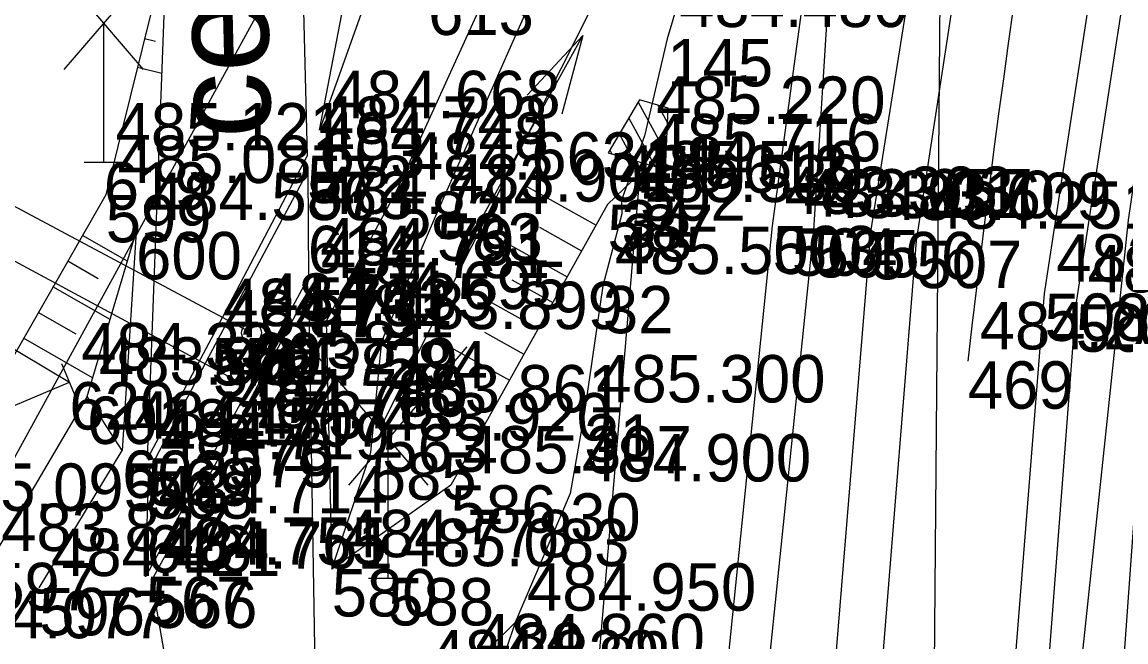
# Model space of a CAD drawing. Extents: x -874038 to -859694, y -1059487 to -1049069.
# Drawn here: x -866901.73 to -866873.81, y -1050811.61 to -1050795.92 of the extents above; entities that cross this region are included whole.
import ezdxf

# ---------------------------------------------------------------- set-up
doc = ezdxf.new("R2010")
doc.units = 0
for name, color, linetype in [('Vrstva 1', 7, 'Continuous'), ('Vrstva 13', 7, 'Continuous'), ('Vrstva 23', 7, 'Continuous'), ('Vrstva 28', 7, 'Continuous'), ('Vrstva 31', 7, 'Continuous'), ('Vrstva 32', 7, 'Continuous'), ('Vrstva 4', 7, 'Continuous'), ('Vrstva 44', 7, 'Continuous'), ('Vrstva 48', 7, 'Continuous'), ('Vrstva 49', 7, 'Continuous'), ('Vrstva 51', 7, 'Continuous'), ('Vrstva 6', 7, 'Continuous'), ('Vrstva 60', 7, 'Continuous'), ('Vrstva 61', 7, 'Continuous'), ('Vrstva 63', 7, 'Continuous'), ('Vrstva 7', 7, 'Continuous')]:
    doc.layers.add(name, color=color, linetype=linetype)

msp = doc.modelspace()

# ---------------------------------------------------------------- linework, layer by layer
at = {"layer": 'Vrstva 1'}
msp.add_line((-866954.595, -1050772.5), (-866895.93, -1050803.784), dxfattribs=at)
msp.add_circle((-866895.93, -1050803.784), 0.25, dxfattribs=at)
msp.add_arc((-866539.48, -1050843.456), 340.562, 163.73547, 173.43306, dxfattribs=at)
at = {"layer": 'Vrstva 13'}
for p, q in [((-866882.745, -1050801.081), (-866881.765, -1050793.85)), ((-866881.706, -1050801.186), (-866881.246, -1050793.897)), ((-866890.45, -1050801.514), (-866887.55, -1050796.262)), ((-866884.839, -1050821.549), (-866882.745, -1050801.081)), ((-866883.811, -1050821.656), (-866881.706, -1050801.186)), ((-866873.377, -1050805.329), (-866874.96, -1050827.043))]:
    msp.add_line(p, q, dxfattribs=at)
for points in [[(-866883.26, -1050790.618), (-866884.83, -1050791.288), (-866885.841, -1050792.599), (-866892.622, -1050806.103)], [(-866888.954, -1050797.77), (-866887.55, -1050796.262), (-866888.079, -1050798.253)]]:
    msp.add_lwpolyline(points, dxfattribs=at)
at = {"layer": 'Vrstva 23'}
msp.add_lwpolyline([(-866860.091, -1050744.519), (-866863.217, -1050755.466), (-866865.293, -1050757.745), (-866868.888, -1050772.679), (-866871.977, -1050788.759), (-866873.748, -1050800.936), (-866875.048, -1050813.205), (-866876.041, -1050829.553), (-866876.177, -1050845.923), (-866875.472, -1050862.297), (-866873.902, -1050878.655), (-866871.491, -1050894.865), (-866868.278, -1050910.955), (-866864.193, -1050926.852), (-866859.318, -1050942.487)], dxfattribs=at)
at = {"layer": 'Vrstva 28'}
for points in [[(-866881.37, -1050788.45), (-866881.18, -1050787.98), (-866881.44, -1050787.55), (-866882.31, -1050787.39), (-866883.05, -1050788.18), (-866884.05, -1050790.89), (-866884.17, -1050792.18), (-866885.41, -1050796.35), (-866885.99, -1050798.8), (-866886.57, -1050800.43), (-866886.56, -1050800.78), (-866887.04, -1050802.6), (-866887.51, -1050805.85), (-866887.87, -1050807.85), (-866889.26, -1050811.12), (-866890.17, -1050813.82), (-866890.72, -1050816.67), (-866890.58, -1050818.77), (-866890.54, -1050824.2), (-866890.49, -1050831.84), (-866890.38, -1050847.8), (-866888.25, -1050865.72)], [(-866881.37, -1050788.45), (-866881.18, -1050787.98), (-866881.44, -1050787.55), (-866882.31, -1050787.39), (-866883.05, -1050788.18), (-866884.05, -1050790.89), (-866884.17, -1050792.18), (-866885.41, -1050796.35), (-866885.99, -1050798.8), (-866886.57, -1050800.43), (-866886.56, -1050800.78), (-866887.04, -1050802.6), (-866887.51, -1050805.85), (-866887.87, -1050807.85), (-866889.26, -1050811.12)], [(-866889.26, -1050811.12), (-866890.56, -1050812.4), (-866891.72, -1050812.81)]]:
    msp.add_lwpolyline(points, dxfattribs=at)
at = {"layer": 'Vrstva 31'}
for p, q in [((-866886.113, -1050797.89), (-866886.903, -1050799.229)), ((-866886.148, -1050797.948), (-866885.44, -1050799.252)), ((-866885.392, -1050798.103), (-866886.113, -1050797.89)), ((-866885.647, -1050798.027), (-866885.407, -1050798.47)), ((-866886.387, -1050798.353), (-866885.719, -1050799.579)), ((-866885.457, -1050799.656), (-866885.392, -1050798.103)), ((-866886.624, -1050798.755), (-866886.264, -1050799.418)), ((-866886.863, -1050799.16), (-866886.81, -1050799.256)), ((-866886.903, -1050799.229), (-866885.457, -1050799.656))]:
    msp.add_line(p, q, dxfattribs=at)
at = {"layer": 'Vrstva 32'}
for points in [[(-866881.37, -1050788.45), (-866881.18, -1050787.98), (-866881.44, -1050787.55), (-866882.31, -1050787.39), (-866883.05, -1050788.18), (-866884.05, -1050790.89), (-866884.17, -1050792.18), (-866885.41, -1050796.35), (-866885.99, -1050798.8), (-866886.57, -1050800.43), (-866886.56, -1050800.78), (-866887.04, -1050802.6), (-866887.51, -1050805.85), (-866887.87, -1050807.85), (-866889.26, -1050811.12), (-866890.17, -1050813.82), (-866890.72, -1050816.67), (-866890.58, -1050818.77)], [(-866881.37, -1050788.45), (-866881.18, -1050787.98), (-866881.44, -1050787.55), (-866882.31, -1050787.39), (-866883.05, -1050788.18), (-866884.05, -1050790.89), (-866884.17, -1050792.18), (-866885.41, -1050796.35), (-866885.99, -1050798.8), (-866886.57, -1050800.43), (-866886.56, -1050800.78), (-866887.04, -1050802.6), (-866887.51, -1050805.85), (-866887.87, -1050807.85), (-866889.26, -1050811.12), (-866890.17, -1050813.82), (-866890.72, -1050816.67), (-866890.58, -1050818.77), (-866890.49, -1050831.84), (-866890.38, -1050847.8), (-866888.25, -1050865.72)], [(-866881.37, -1050788.45), (-866881.18, -1050787.98), (-866881.44, -1050787.55), (-866882.31, -1050787.39), (-866883.05, -1050788.18), (-866884.05, -1050790.89), (-866884.17, -1050792.18), (-866885.41, -1050796.35), (-866885.99, -1050798.8), (-866886.57, -1050800.43), (-866886.56, -1050800.78), (-866887.04, -1050802.6), (-866887.51, -1050805.85), (-866887.87, -1050807.85), (-866889.26, -1050811.12)], [(-866889.26, -1050811.12), (-866890.56, -1050812.4), (-866891.72, -1050812.81)]]:
    msp.add_lwpolyline(points, dxfattribs=at)
at = {"layer": 'Vrstva 4'}
for p, q in [((-866874.869, -1050762.04), (-866892.274, -1050800.212)), ((-866891.238, -1050800.767), (-866874.734, -1050763.477)), ((-866876.724, -1050779.104), (-866880.273, -1050801.234)), ((-866879.105, -1050801.456), (-866875.741, -1050779.509)), ((-866871.451, -1050779.65), (-866875.077, -1050803.067)), ((-866875.867, -1050802.793), (-866872.377, -1050779.959)), ((-866901.668, -1050793.623), (-866898.668, -1050797.123)), ((-866900.668, -1050797.123), (-866897.668, -1050793.623)), ((-866899.668, -1050799.473), (-866899.668, -1050795.973)), ((-866900.168, -1050799.473), (-866899.168, -1050799.473)), ((-866896.908, -1050804.202), (-866894.504, -1050799.708)), ((-866894.504, -1050799.708), (-866894.488, -1050802.383)), ((-866892.274, -1050800.212), (-866894.044, -1050803.489)), ((-866904.108, -1050800.796), (-866896.518, -1050804.882)), ((-866892.631, -1050803.995), (-866891.238, -1050800.767)), ((-866900.09, -1050805.401), (-866898.851, -1050801.235)), ((-866898.851, -1050801.235), (-866899.201, -1050806.767)), ((-866880.273, -1050801.234), (-866882.525, -1050828.821)), ((-866881.311, -1050828.858), (-866879.105, -1050801.456)), ((-866894.488, -1050802.383), (-866896.556, -1050806.207)), ((-866877.931, -1050828.807), (-866875.867, -1050802.793)), ((-866875.077, -1050803.067), (-866877.028, -1050828.61)), ((-866894.044, -1050803.489), (-866893.901, -1050809.767)), ((-866898.531, -1050807.291), (-866896.908, -1050804.202)), ((-866894.471, -1050804.144), (-866891.471, -1050807.644)), ((-866893.471, -1050807.644), (-866890.471, -1050804.144)), ((-866892.913, -1050806.813), (-866892.631, -1050803.995)), ((-866900.09, -1050805.401), (-866902.564, -1050809.609)), ((-866899.201, -1050806.767), (-866900.09, -1050805.401)), ((-866896.556, -1050806.207), (-866898.608, -1050809.959)), ((-866892.471, -1050809.994), (-866892.471, -1050806.494)), ((-866901.302, -1050810.243), (-866899.201, -1050806.767)), ((-866893.901, -1050809.767), (-866892.913, -1050806.813)), ((-866898.608, -1050809.959), (-866898.531, -1050807.291)), ((-866892.971, -1050809.994), (-866891.971, -1050809.994))]:
    msp.add_line(p, q, dxfattribs=at)
msp.add_lwpolyline([(-866891.558, -1050791.236), (-866894.209, -1050798.657), (-866892.733, -1050790.985)], dxfattribs=at)
at = {"layer": 'Vrstva 44'}
msp.add_lwpolyline([(-866912.752, -1050826.723), (-866890.904, -1050786.8), (-866874.15, -1050746.784), (-866858.678, -1050710.211), (-866845.122, -1050668.894)], dxfattribs=at)
at = {"layer": 'Vrstva 48'}
for p, q in [((-866898.355, -1050796.414), (-866898.636, -1050796.345)), ((-866898.197, -1050797.225), (-866898.817, -1050797.071)), ((-866889.023, -1050800.05), (-866887.212, -1050801.061)), ((-866888.647, -1050801.118), (-866887.578, -1050801.715)), ((-866899.071, -1050801.975), (-866900.207, -1050801.324)), ((-866889.696, -1050801.39), (-866887.943, -1050802.369)), ((-866899.806, -1050802.418), (-866900.58, -1050801.975)), ((-866889.343, -1050802.446), (-866888.309, -1050803.024)), ((-866899.51, -1050803.452), (-866900.953, -1050802.625)), ((-866890.37, -1050802.731), (-866888.674, -1050803.678)), ((-866900.368, -1050803.825), (-866901.326, -1050803.276)), ((-866899.95, -1050804.929), (-866901.699, -1050803.927)), ((-866890.039, -1050803.774), (-866889.039, -1050804.332)), ((-866891.043, -1050804.072), (-866889.405, -1050804.987))]:
    msp.add_line(p, q, dxfattribs=at)
at = {"layer": 'Vrstva 49'}
for points in [[(-866898.079, -1050794.1), (-866899.618, -1050800.297), (-866904.374, -1050808.594)], [(-866887.646, -1050855.275), (-866888.765, -1050831.266), (-866886.099, -1050799.75), (-866886.924, -1050800.544), (-866890.89, -1050807.647), (-866893.901, -1050809.767)]]:
    msp.add_lwpolyline(points, dxfattribs=at)
at = {"layer": 'Vrstva 51'}
for p, q in [((-866898.565, -1050806.967), (-866898.079, -1050794.1)), ((-866894.652, -1050794.2), (-866894.525, -1050799.306)), ((-866894.525, -1050799.306), (-866896.944, -1050803.919)), ((-866894.477, -1050802.704), (-866896.511, -1050806.501)), ((-866894.277, -1050814.763), (-866894.477, -1050802.704)), ((-866896.944, -1050803.919), (-866898.565, -1050806.967)), ((-866896.511, -1050806.501), (-866898.458, -1050810.057)), ((-866898.458, -1050810.057), (-866897.206, -1050817.362))]:
    msp.add_line(p, q, dxfattribs=at)
at = {"layer": 'Vrstva 6'}
msp.add_line((-866906.348, -1050801.577), (-866900.537, -1050805.036), dxfattribs=at)
at = {"layer": 'Vrstva 60'}
for p, q in [((-866885.41, -1050796.35), (-866885.41, -1050796.35)), ((-866894.209, -1050798.657), (-866894.209, -1050798.657)), ((-866885.99, -1050798.8), (-866885.99, -1050798.8)), ((-866899.668, -1050799.473), (-866899.668, -1050799.473)), ((-866894.525, -1050799.306), (-866894.525, -1050799.306)), ((-866894.504, -1050799.708), (-866894.504, -1050799.708)), ((-866886.099, -1050799.75), (-866886.099, -1050799.75)), ((-866899.618, -1050800.297), (-866899.618, -1050800.297)), ((-866892.274, -1050800.212), (-866892.274, -1050800.212)), ((-866886.924, -1050800.544), (-866886.924, -1050800.544)), ((-866886.57, -1050800.43), (-866886.57, -1050800.43)), ((-866891.238, -1050800.767), (-866891.238, -1050800.767)), ((-866886.56, -1050800.78), (-866886.56, -1050800.78)), ((-866894.506, -1050801.079), (-866894.506, -1050801.079)), ((-866882.745, -1050801.081), (-866882.745, -1050801.081)), ((-866882.26, -1050801.145), (-866882.26, -1050801.145)), ((-866898.851, -1050801.235), (-866898.851, -1050801.235)), ((-866881.706, -1050801.186), (-866881.706, -1050801.186)), ((-866880.273, -1050801.234), (-866880.273, -1050801.234)), ((-866879.105, -1050801.456), (-866879.105, -1050801.456)), ((-866894.488, -1050802.383), (-866894.488, -1050802.383)), ((-866894.477, -1050802.704), (-866894.477, -1050802.704)), ((-866887.04, -1050802.6), (-866887.04, -1050802.6)), ((-866875.867, -1050802.793), (-866875.867, -1050802.793)), ((-866875.077, -1050803.067), (-866875.077, -1050803.067)), ((-866894.044, -1050803.489), (-866894.044, -1050803.489)), ((-866896.944, -1050803.919), (-866896.944, -1050803.919)), ((-866895.93, -1050803.784), (-866895.93, -1050803.784)), ((-866896.908, -1050804.202), (-866896.908, -1050804.202)), ((-866892.631, -1050803.995), (-866892.631, -1050803.995)), ((-866877.806, -1050804.508), (-866877.806, -1050804.508)), ((-866900.537, -1050805.036), (-866900.537, -1050805.036)), ((-866900.09, -1050805.401), (-866900.09, -1050805.401)), ((-866896.809, -1050805.421), (-866896.809, -1050805.421)), ((-866887.51, -1050805.85), (-866887.51, -1050805.85)), ((-866892.622, -1050806.103), (-866892.622, -1050806.103)), ((-866896.556, -1050806.207), (-866896.556, -1050806.207)), ((-866896.511, -1050806.501), (-866896.511, -1050806.501)), ((-866899.201, -1050806.767), (-866899.201, -1050806.767)), ((-866898.565, -1050806.967), (-866898.565, -1050806.967)), ((-866892.913, -1050806.813), (-866892.913, -1050806.813)), ((-866898.531, -1050807.291), (-866898.531, -1050807.291)), ((-866890.89, -1050807.647), (-866890.89, -1050807.647)), ((-866887.87, -1050807.85), (-866887.87, -1050807.85)), ((-866898.585, -1050808.656), (-866898.585, -1050808.656)), ((-866893.901, -1050809.767), (-866893.901, -1050809.767)), ((-866898.608, -1050809.959), (-866898.608, -1050809.959)), ((-866898.458, -1050810.057), (-866898.458, -1050810.057)), ((-866892.471, -1050809.994), (-866892.471, -1050809.994)), ((-866901.302, -1050810.243), (-866901.302, -1050810.243)), ((-866889.26, -1050811.12), (-866889.26, -1050811.12))]:
    msp.add_line(p, q, dxfattribs=at)
at = {"layer": 'Vrstva 63'}
msp.add_line((-866879.309, -1050890.061), (-866878.429, -1050785.654), dxfattribs=at)
at = {"layer": 'Vrstva 7'}
for p, q in [((-866900.342, -1050805.497), (-866900.732, -1050804.575)), ((-866903.3, -1050806.205), (-866900.537, -1050805.036))]:
    msp.add_line(p, q, dxfattribs=at)

# ---------------------------------------------------------------- texts
at = {"layer": 'Vrstva 51'}
msp.add_text('cesta', height=2.5, rotation=91.4248, dxfattribs=at).set_placement((-866895.436, -1050798.841))
at = {"layer": 'Vrstva 60'}
for s, p in [('613', (-866891.463, -1050796.251)), ('145', (-866885.41, -1050797.55)), ('603', (-866894.209, -1050799.857)), ('144', (-866885.99, -1050800)), ('619', (-866899.668, -1050800.673)), ('572', (-866894.525, -1050800.506)), ('573', (-866894.504, -1050800.908)), ('502', (-866886.099, -1050800.95)), ('599', (-866899.618, -1050801.497)), ('582', (-866892.274, -1050801.412)), ('587', (-866886.924, -1050801.744)), ('34', (-866886.57, -1050801.63)), ('583', (-866891.238, -1050801.967)), ('33', (-866886.56, -1050801.98)), ('614', (-866894.506, -1050802.279)), ('503', (-866882.745, -1050802.281)), ('504', (-866882.26, -1050802.345)), ('600', (-866898.851, -1050802.435)), ('505', (-866881.706, -1050802.386)), ('506', (-866880.273, -1050802.434)), ('507', (-866879.105, -1050802.656)), ('574', (-866894.488, -1050803.583)), ('575', (-866894.477, -1050803.904)), ('32', (-866887.04, -1050803.8)), ('508', (-866875.867, -1050803.993)), ('509', (-866875.077, -1050804.267)), ('581', (-866894.044, -1050804.689)), ('576', (-866896.944, -1050805.119)), ('603', (-866895.93, -1050804.984)), ('577', (-866896.908, -1050805.402)), ('584', (-866892.631, -1050805.195)), ('469', (-866877.806, -1050805.708)), ('620', (-866900.537, -1050806.236)), ('601', (-866900.09, -1050806.601)), ('615', (-866896.809, -1050806.621)), ('31', (-866887.51, -1050807.05)), ('563', (-866892.622, -1050807.303)), ('578', (-866896.556, -1050807.407)), ('579', (-866896.511, -1050807.701)), ('602', (-866899.201, -1050807.967)), ('569', (-866898.565, -1050808.167)), ('585', (-866892.913, -1050808.013)), ('568', (-866898.531, -1050808.491)), ('586', (-866890.89, -1050808.847)), ('30', (-866887.87, -1050809.05)), ('616', (-866898.585, -1050809.856)), ('597', (-866902.564, -1050810.809)), ('580', (-866893.901, -1050810.967)), ('567', (-866898.608, -1050811.159)), ('566', (-866898.458, -1050811.257)), ('588', (-866892.471, -1050811.194)), ('596', (-866901.302, -1050811.443)), ('29', (-866889.26, -1050812.32))]:
    msp.add_text(s, height=1.2, dxfattribs=at).set_placement(p)
at = {"layer": 'Vrstva 61'}
for s, p in [('484.480', (-866885.11, -1050796.05)), ('484.668', (-866893.909, -1050798.357)), ('485.220', (-866885.69, -1050798.5)), ('484.743', (-866894.225, -1050799.006)), ('485.121', (-866899.368, -1050799.173)), ('484.748', (-866894.204, -1050799.408)), ('485.716', (-866885.799, -1050799.45)), ('485.081', (-866899.318, -1050799.997)), ('484.663', (-866891.974, -1050799.912)), ('485.510', (-866886.27, -1050800.13)), ('485.612', (-866886.624, -1050800.244)), ('483.901', (-866890.938, -1050800.467)), ('485.530', (-866886.26, -1050800.48)), ('484.586', (-866898.551, -1050800.935)), ('484.744', (-866894.206, -1050800.779)), ('483.303', (-866882.445, -1050800.781)), ('483.057', (-866881.96, -1050800.845)), ('483.310', (-866881.406, -1050800.886)), ('483.609', (-866879.973, -1050800.934)), ('484.251', (-866878.805, -1050801.156)), ('484.791', (-866894.188, -1050802.083)), ('485.500', (-866886.74, -1050802.3)), ('484.781', (-866894.177, -1050802.404)), ('483.943', (-866875.567, -1050802.493)), ('483.318', (-866874.777, -1050802.767)), ('484.695', (-866893.744, -1050803.189)), ('484.735', (-866895.63, -1050803.484)), ('484.732', (-866896.644, -1050803.619)), ('483.899', (-866892.331, -1050803.695)), ('484.731', (-866896.608, -1050803.902)), ('484.201', (-866877.506, -1050804.208)), ('484.338', (-866900.237, -1050804.736)), ('483.931', (-866899.79, -1050805.101)), ('484.729', (-866896.509, -1050805.121)), ('485.300', (-866887.21, -1050805.55)), ('484.780', (-866896.256, -1050805.907)), ('483.861', (-866892.322, -1050805.803)), ('484.783', (-866896.211, -1050806.201)), ('484.473', (-866898.901, -1050806.467)), ('483.920', (-866892.613, -1050806.513)), ('484.707', (-866898.265, -1050806.667)), ('484.719', (-866898.231, -1050806.991)), ('485.307', (-866890.59, -1050807.347)), ('484.900', (-866887.57, -1050807.55)), ('485.095', (-866904.074, -1050808.294)), ('484.714', (-866898.285, -1050808.356)), ('483.827', (-866902.264, -1050809.309)), ('484.778', (-866893.601, -1050809.467)), ('484.755', (-866898.308, -1050809.659)), ('484.761', (-866898.158, -1050809.757)), ('485.083', (-866892.171, -1050809.694)), ('484.421', (-866901.002, -1050809.943)), ('484.950', (-866888.96, -1050810.82)), ('484.077', (-866903.859, -1050811.517)), ('484.860', (-866890.26, -1050812.1)), ('484.830', (-866891.42, -1050812.51))]:
    msp.add_text(s, height=1.2, dxfattribs=at).set_placement(p)

doc.saveas('drawing.dxf')
